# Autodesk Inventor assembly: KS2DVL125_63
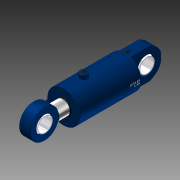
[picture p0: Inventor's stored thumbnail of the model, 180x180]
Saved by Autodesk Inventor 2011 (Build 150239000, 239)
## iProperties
Created: 2010-11
Document SubType Name: Assembly
Designer: TB
Mass: 566.294 g
Surface Area: 1153.75 cm^2
Volume: 566.294 cm^3
Density: 1 g/cm^3
Description: KS2DVL 125/63 - 100 mm
Slaglengde: 100,000 mm
Author: TB
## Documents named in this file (6)
- C:\Vault\Sylinderteknikk\Projects_ST\3D.nettkatalog\KS2-Series\KS2DVL\KS2DVL125_63\KS2DVL125_63.iam
- C:\Vault\Sylinderteknikk\Projects_ST\3D.nettkatalog\KS2-Series\KS2DVL\KS2DVL125_63\KS2DVL125_63_stang.ipt
- C:\Vault\Sylinderteknikk\Projects_ST\3D.nettkatalog\KS2-Series\KS2DVL\KS2DVL125_63\KS2DVL125_63_Parameters.ipt
- C:\Vault\Sylinderteknikk\Projects_ST\3D.nettkatalog\KS2-Series\KS2DVL\KS2DVL125_63\KS2DVL125_63_body..ipt
- C:\Vault\Sylinderteknikk\Projects_ST\Øyer\Klinkby.KS.Øyer\KS.60.eye.komplett\KS.60.eye.komplett.ipt
- C:\Vault\Sylinderteknikk\Projects_ST\Øyer\Klinkby.KS.Øyer\KS.60.eye.komplett\Kule60HO.ipt
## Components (5 placed, 5 different names)
1. KS2DVL125_63_Parameters:3
2. KS2DVL125_63_stang:1 — Mate:1, FriMate:2, Mate:3, Insert:1
3. KS2DVL125_63_body.:1 — Mate:1, FriMate:2, Mate:3, Angle:1, Insert:2
4. KS.60.eye.komplett:1 — Insert:1, Angle:1
5. Kule60HO:1 — Insert:2
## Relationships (6: Mate 3, Insert 2, Angle 1)
- Mate:1: KS2DVL125_63_stang:1 ↔ KS2DVL125_63_body.:1
- FriMate:2 [Mate]: KS2DVL125_63_stang:1 ↔ KS2DVL125_63_body.:1
- Mate:3: KS2DVL125_63_stang:1 ↔ KS2DVL125_63_body.:1
- Insert:1: KS2DVL125_63_stang:1 ↔ KS.60.eye.komplett:1
- Angle:1: KS2DVL125_63_body.:1 ↔ KS.60.eye.komplett:1
- Insert:2: KS2DVL125_63_body.:1 ↔ Kule60HO:1
## Named parameters: Forlengelse_rør = 0, Vinkel_Minusport = 0
